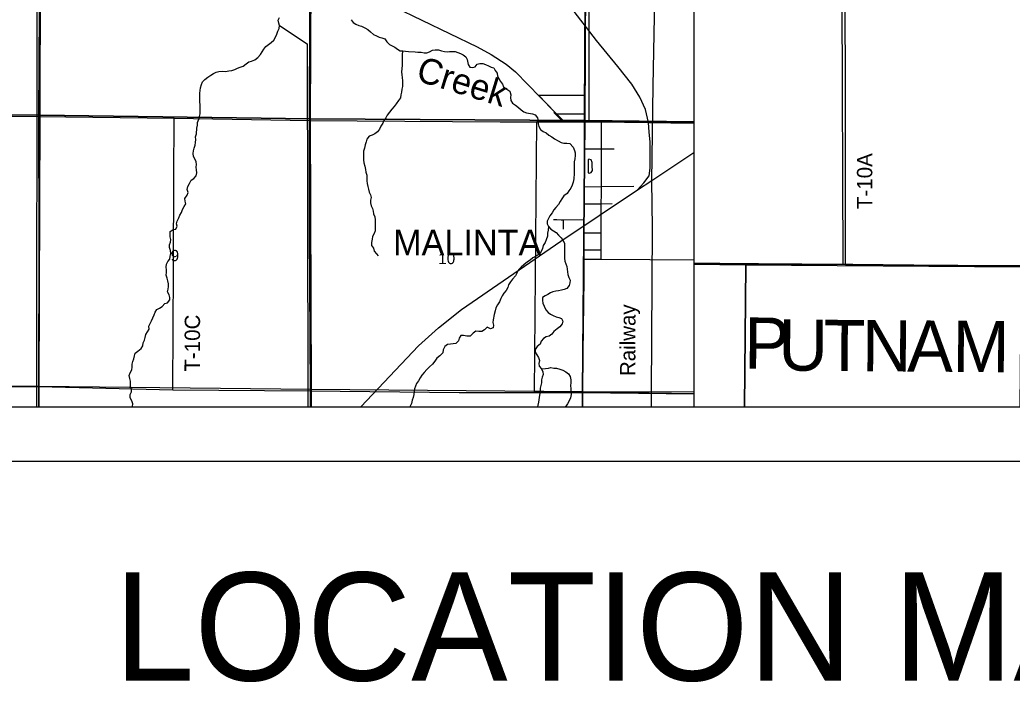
# Model space of a CAD drawing. Extents: x -6.2 to 37.4, y 0.2 to 22.2.
# Drawn here: x 3.834 to 5.67, y 13.798 to 15.024 of the extents above; entities that cross this region are included whole.
import ezdxf

# ---------------------------------------------------------------- set-up
doc = ezdxf.new("R2010")
doc.units = 0
for name, color, linetype in [('GM_X_City_Street', 7, 'Continuous'), ('GM_X_Corporation', 7, 'Continuous'), ('GM_X_Corporation_Text', 7, 'Continuous'), ('GM_X_County_Road', 7, 'Continuous'), ('GM_X_County_Text', 7, 'Continuous'), ('GM_X_Minor_Lake', 7, 'Continuous'), ('GM_X_Minor_River', 7, 'Continuous'), ('GM_X_Minor_River_Text', 7, 'Continuous'), ('GM_X_Rail_Line', 7, 'Continuous'), ('GM_X_Rail_Line_Text', 7, 'Continuous'), ('GM_X_Section', 7, 'Continuous'), ('GM_X_Section_Text', 7, 'Continuous'), ('GM_X_State_Route', 7, 'Continuous'), ('GM_X_Township_Road', 7, 'Continuous'), ('GM_X_Township_Road_Text', 7, 'Continuous'), ('GM_X_US_Shield', 7, 'Continuous'), ('SH_Border', 7, 'Continuous'), ('SH_Cut_Line', 7, 'Continuous'), ('SH_Data', 7, 'Continuous'), ('SH_Text', 7, 'Continuous')]:
    doc.layers.add(name, color=color, linetype=linetype)

msp = doc.modelspace()

# ---------------------------------------------------------------- linework, layer by layer
at = {"layer": 'GM_X_City_Street'}
for p, q in [((4.8397, 14.6538), (4.8779, 14.6545)), ((4.8397, 14.6365), (4.8397, 14.6538)), ((4.8779, 14.6294), (4.9092, 14.6294)), ((4.8777, 14.5983), (4.909, 14.5983))]:
    msp.add_line(p, q, dxfattribs=at)
for points in [[(4.909, 14.5807), (4.909, 14.5983), (4.9092, 14.6294), (4.9094, 14.6833), (4.9095, 14.7017), (4.9095, 14.7152), (4.9095, 14.785), (4.9096, 14.8348)], [(4.8784, 14.7848), (4.9095, 14.785), (4.933, 14.7851)], [(4.8782, 14.7148), (4.9095, 14.7152), (4.9695, 14.7159)], [(4.8781, 14.6829), (4.9094, 14.6833), (4.9292, 14.6836)], [(4.8207, 14.6542), (4.8272, 14.654), (4.835, 14.6537), (4.8397, 14.6538)], [(4.8777, 14.5808), (4.909, 14.5807), (4.9991, 14.5804), (5.0809, 14.5799)]]:
    msp.add_lwpolyline(points, dxfattribs=at)
at = {"layer": 'GM_X_Corporation'}
msp.add_lwpolyline([(5.0809, 14.3317), (4.8749, 14.3347), (4.7857, 14.3347), (4.7899, 14.8354), (4.8382, 14.8354), (4.8216, 14.8523), (4.8242, 14.8523), (4.793, 14.8843), (4.8787, 14.8843), (4.8785, 14.8493), (4.8271, 14.8493), (4.8407, 14.8354), (4.8785, 14.8354), (5.0809, 14.8328)], dxfattribs=at)
at = {"layer": 'GM_X_County_Road'}
for p, q in [((4.7964, 14.8806), (4.8237, 14.8526)), ((4.8237, 14.8526), (4.8271, 14.8491)), ((4.8271, 14.8491), (4.8407, 14.8351)), ((4.836, 14.8351), (4.8407, 14.8351)), ((4.8407, 14.8351), (4.8786, 14.8352))]:
    msp.add_line(p, q, dxfattribs=at)
for points in [[(4.3712, 15.2058), (4.4704, 15.1311), (4.475, 15.1261), (4.4823, 15.114), (4.5079, 15.0602), (4.5117, 15.0558), (4.5262, 15.0474), (4.6796, 14.9736), (4.7056, 14.9596), (4.7333, 14.9416), (4.7507, 14.9275), (4.7964, 14.8806)], [(3.3737, 14.8502), (3.5993, 14.8481), (3.6217, 14.8478), (3.869, 14.8445), (4.1193, 14.8414), (4.3697, 14.8376), (4.7222, 14.8351), (4.7789, 14.8351)], [(4.7789, 14.8351), (4.7975, 14.8351), (4.8265, 14.8351)], [(4.8265, 14.8351), (4.8312, 14.8351), (4.836, 14.8351)], [(4.8786, 14.8352), (4.9096, 14.8348), (5.0809, 14.8325)], [(5.0809, 14.5729), (5.129, 14.5725), (5.2005, 14.5717), (5.3613, 14.5708)], [(5.3613, 14.5708), (5.3746, 14.5707), (5.488, 14.5696), (5.5689, 14.569), (5.6863, 14.5681)]]:
    msp.add_lwpolyline(points, dxfattribs=at)
at = {"layer": 'GM_X_Minor_Lake'}
msp.add_line((4.885, 14.7624), (4.8854, 14.7408), dxfattribs=at)
msp.add_lwpolyline([(4.8854, 14.7408), (4.8867, 14.7402), (4.8906, 14.7412), (4.893, 14.7449), (4.8928, 14.7527), (4.8927, 14.7599), (4.8907, 14.7645), (4.8866, 14.7656), (4.885, 14.7649), (4.885, 14.7624)], dxfattribs=at)
at = {"layer": 'GM_X_Minor_River'}
msp.add_line((3.8653, 15.2244), (3.8642, 14.3074), dxfattribs=at)
for points in [[(4.8897, 16.0915), (4.8869, 16.0485), (4.8784, 15.3818), (4.886, 15.3582), (4.8861, 14.8386)], [(5.4281, 15.4944), (5.3538, 15.4752), (5.3544, 15.0595), (5.3561, 14.5724)], [(4.1816, 14.9173), (4.187, 14.9211), (4.1919, 14.9244), (4.1967, 14.9269), (4.202, 14.9279), (4.2077, 14.9287), (4.2142, 14.9283), (4.2201, 14.9291), (4.226, 14.9296), (4.2313, 14.932), (4.2365, 14.9339), (4.2415, 14.936), (4.2467, 14.9381), (4.2521, 14.942), (4.257, 14.9456), (4.2625, 14.947), (4.2683, 14.9497), (4.2739, 14.9542), (4.2788, 14.9592), (4.2818, 14.9641), (4.2852, 14.9695), (4.2886, 14.9745), (4.2986, 14.9818), (4.3035, 14.9862), (4.3067, 14.9914), (4.3088, 14.9972), (4.3112, 15.0027), (4.3135, 15.0075), (4.3142, 15.0128), (4.3126, 15.0176), (4.3114, 15.0228), (4.3139, 15.0276)], [(4.4463, 15.0237), (4.4503, 15.0187), (4.4553, 15.0153), (4.4606, 15.0131), (4.466, 15.0118), (4.4722, 15.0088), (4.4774, 15.0054), (4.4822, 15.0014), (4.4881, 14.9967), (4.4932, 14.9939), (4.4984, 14.9917), (4.5033, 14.9902), (4.5086, 14.9883), (4.5127, 14.9827), (4.5173, 14.9778), (4.5222, 14.9756), (4.5271, 14.9732), (4.5322, 14.9691), (4.5375, 14.9661), (4.5422, 14.9661), (4.5473, 14.9658), (4.5528, 14.965)], [(4.3142, 15.0128), (4.3655, 14.9791), (4.3665, 14.3408), (4.3664, 14.3074)], [(4.5422, 14.9661), (4.5411, 14.9608), (4.5409, 14.9559), (4.541, 14.9498), (4.5408, 14.9445), (4.541, 14.9394), (4.5405, 14.9333), (4.5397, 14.9269), (4.5401, 14.9222), (4.5409, 14.9166), (4.5415, 14.9111), (4.5413, 14.9054), (4.5414, 14.9001), (4.5406, 14.8952), (4.5397, 14.8899), (4.5388, 14.885), (4.5377, 14.8794), (4.5339, 14.8742), (4.5296, 14.8684), (4.5264, 14.8634), (4.5221, 14.8584), (4.5176, 14.853), (4.5132, 14.8475), (4.511, 14.8426), (4.5068, 14.8374), (4.5054, 14.8325), (4.5018, 14.8267), (4.4993, 14.8211), (4.4954, 14.8161), (4.4905, 14.8125), (4.4852, 14.8105), (4.4798, 14.8082), (4.4757, 14.8028), (4.4742, 14.7976), (4.4725, 14.7923), (4.471, 14.7863), (4.4695, 14.7804), (4.4692, 14.7704), (4.4692, 14.7645), (4.4703, 14.7588), (4.4717, 14.7529), (4.4734, 14.7468), (4.4738, 14.7418), (4.4757, 14.7361), (4.4758, 14.7313), (4.4756, 14.726), (4.476, 14.7209), (4.4772, 14.7153), (4.4784, 14.7106), (4.4801, 14.7048), (4.4826, 14.6998), (4.4838, 14.6949), (4.4825, 14.69), (4.4825, 14.6848), (4.4839, 14.6797), (4.4862, 14.6745), (4.4876, 14.6697), (4.4882, 14.6649), (4.4901, 14.6592), (4.4909, 14.6537), (4.4913, 14.6485), (4.4913, 14.6434), (4.491, 14.6381), (4.4912, 14.6334), (4.489, 14.6285), (4.4863, 14.6229), (4.4854, 14.6176), (4.4841, 14.6118), (4.4843, 14.6063), (4.4881, 14.601), (4.4891, 14.5957), (4.4933, 14.5908), (4.4968, 14.5871)], [(4.5528, 14.965), (4.5649, 14.9647), (4.5702, 14.9638), (4.5763, 14.9636), (4.5815, 14.9623), (4.5865, 14.9627), (4.5914, 14.9641), (4.5968, 14.9672), (4.6022, 14.9683), (4.6082, 14.9678), (4.6135, 14.9661), (4.6192, 14.965), (4.6241, 14.9647), (4.6288, 14.9653), (4.634, 14.9653), (4.6389, 14.965), (4.6438, 14.9631), (4.6488, 14.9613), (4.6537, 14.9591), (4.6585, 14.9553), (4.6614, 14.9505), (4.663, 14.941), (4.6659, 14.9359), (4.6708, 14.9354), (4.6759, 14.9364), (4.6799, 14.9414), (4.6847, 14.9428), (4.6902, 14.9426), (4.6954, 14.941), (4.7005, 14.9385), (4.7055, 14.9363), (4.7104, 14.9346), (4.7133, 14.9298), (4.7167, 14.925), (4.7175, 14.9196), (4.72, 14.9148), (4.7231, 14.9098), (4.7267, 14.9048), (4.7287, 14.8996), (4.7344, 14.8954), (4.7402, 14.8918), (4.7421, 14.8851), (4.7417, 14.8802), (4.7418, 14.8745), (4.7452, 14.8695), (4.7504, 14.8657), (4.7562, 14.8612), (4.7611, 14.8571), (4.766, 14.8535), (4.771, 14.8513), (4.782, 14.8498), (4.7869, 14.848), (4.7914, 14.8422), (4.7924, 14.8368), (4.7924, 14.8313), (4.7938, 14.8262), (4.797, 14.8206), (4.8018, 14.817), (4.8075, 14.8144), (4.8126, 14.8102), (4.818, 14.8071), (4.8231, 14.8035), (4.8294, 14.7999), (4.835, 14.7967), (4.8403, 14.7956), (4.8457, 14.7952), (4.8509, 14.7951), (4.8571, 14.7879), (4.8601, 14.7821), (4.8611, 14.7773), (4.8612, 14.7724), (4.8602, 14.7664), (4.8595, 14.7609), (4.859, 14.7558), (4.859, 14.7448), (4.859, 14.7395), (4.8587, 14.7294), (4.8572, 14.7232), (4.8554, 14.7178), (4.8529, 14.7123), (4.8495, 14.7073), (4.846, 14.7025), (4.8403, 14.6977), (4.8364, 14.6925), (4.8334, 14.6875), (4.8304, 14.6817), (4.8255, 14.6767), (4.8217, 14.6719), (4.8185, 14.6665), (4.8142, 14.6611), (4.809, 14.651), (4.8092, 14.6463), (4.8117, 14.6415), (4.8161, 14.6364), (4.8211, 14.633), (4.826, 14.6304), (4.8304, 14.6252), (4.835, 14.6203), (4.8388, 14.6151), (4.8411, 14.6097), (4.8413, 14.6042)], [(4.052, 14.4108), (4.0578, 14.4154), (4.0614, 14.4206), (4.0619, 14.4259), (4.0643, 14.4309), (4.0652, 14.4362), (4.0665, 14.4415), (4.0697, 14.4463), (4.0729, 14.4516), (4.0721, 14.4567), (4.0747, 14.4619), (4.0772, 14.467), (4.0796, 14.4726), (4.0822, 14.4776), (4.0841, 14.4827), (4.0871, 14.4879), (4.0919, 14.4903), (4.0967, 14.4935), (4.1016, 14.4987), (4.1068, 14.5001), (4.1109, 14.5053), (4.1111, 14.51), (4.1101, 14.5151), (4.1065, 14.5204), (4.1078, 14.5253), (4.1085, 14.5302), (4.1086, 14.5349), (4.1075, 14.5405), (4.1061, 14.5454), (4.1046, 14.5513), (4.1047, 14.5563), (4.1047, 14.5612), (4.1043, 14.5662), (4.105, 14.5714), (4.1076, 14.5763), (4.1111, 14.5811), (4.1119, 14.5862), (4.1128, 14.5913), (4.1124, 14.5966), (4.1103, 14.6022), (4.1108, 14.6073), (4.1121, 14.6122), (4.1128, 14.6173), (4.1118, 14.6221), (4.1118, 14.6274), (4.1116, 14.6323), (4.1173, 14.6356), (4.1223, 14.6364), (4.1245, 14.6416), (4.1234, 14.6464), (4.1246, 14.6513), (4.128, 14.6571), (4.1299, 14.662), (4.1325, 14.6674), (4.1348, 14.673), (4.1376, 14.6782), (4.1406, 14.6831), (4.1392, 14.6882), (4.139, 14.693), (4.1432, 14.6991), (4.1448, 14.7042), (4.1431, 14.7097), (4.1444, 14.7154), (4.1478, 14.7208), (4.1504, 14.7268), (4.1555, 14.7303), (4.16, 14.7352), (4.1613, 14.7407), (4.1605, 14.746), (4.1601, 14.7508), (4.1604, 14.7559), (4.1596, 14.7607), (4.1577, 14.7655), (4.1548, 14.7709), (4.1542, 14.7762), (4.1551, 14.7811), (4.1562, 14.7862), (4.1577, 14.7918), (4.1583, 14.7969), (4.159, 14.8022), (4.1584, 14.8072), (4.1604, 14.8126), (4.1608, 14.8234), (4.1621, 14.8289), (4.1626, 14.8338), (4.1648, 14.8396), (4.1663, 14.8447), (4.1674, 14.8496), (4.167, 14.8547), (4.167, 14.8597), (4.167, 14.8661), (4.1668, 14.8716), (4.1666, 14.8771), (4.1665, 14.8821), (4.1669, 14.8877), (4.1672, 14.8927), (4.1681, 14.8981), (4.1694, 14.9038), (4.1717, 14.9087), (4.176, 14.9135), (4.1816, 14.9173)], [(4.8117, 14.6415), (4.8113, 14.6345), (4.81, 14.629), (4.8098, 14.6233), (4.8074, 14.6169), (4.8057, 14.6117), (4.8021, 14.6059), (4.8004, 14.6004), (4.798, 14.5952), (4.7942, 14.5902), (4.7888, 14.5864), (4.7828, 14.5831), (4.7778, 14.5791), (4.7728, 14.576), (4.7663, 14.5705), (4.7614, 14.5659), (4.7564, 14.5611), (4.7538, 14.5561), (4.7505, 14.5501), (4.7449, 14.544), (4.7415, 14.539), (4.7377, 14.5332), (4.7362, 14.5283), (4.7336, 14.5231), (4.7289, 14.5179), (4.7259, 14.5127), (4.7237, 14.5079), (4.7212, 14.502), (4.7174, 14.4963), (4.7144, 14.4911), (4.7133, 14.485), (4.7114, 14.4782), (4.7092, 14.4684), (4.709, 14.4635), (4.7102, 14.4586), (4.7093, 14.4536), (4.7041, 14.4517), (4.6984, 14.4551), (4.6935, 14.4503), (4.6881, 14.4471), (4.6826, 14.447), (4.6775, 14.4476), (4.6722, 14.4441), (4.667, 14.4386), (4.6605, 14.4386), (4.6547, 14.4397), (4.6497, 14.4396), (4.6465, 14.4346), (4.6449, 14.4295), (4.64, 14.4248), (4.6352, 14.4239), (4.6301, 14.4233), (4.6248, 14.4229), (4.6199, 14.4191), (4.6169, 14.4133), (4.616, 14.4076), (4.6109, 14.4023), (4.6052, 14.3975), (4.6016, 14.3919), (4.5969, 14.3868), (4.5913, 14.3814), (4.5868, 14.3766), (4.5819, 14.3711), (4.5773, 14.3661), (4.5745, 14.3612), (4.571, 14.356), (4.5676, 14.3508), (4.5654, 14.3459), (4.5637, 14.3409), (4.5633, 14.3358), (4.5624, 14.3303), (4.5611, 14.3248), (4.5596, 14.3199), (4.5581, 14.3139), (4.5555, 14.3087), (4.5552, 14.3074)], [(4.8413, 14.6042), (4.8415, 14.5979), (4.8415, 14.593), (4.8414, 14.5877), (4.8414, 14.5827), (4.842, 14.5774), (4.8438, 14.5724), (4.8455, 14.5673), (4.8463, 14.5625), (4.8471, 14.5574), (4.8477, 14.5524), (4.8494, 14.5472), (4.8517, 14.542), (4.8514, 14.5369), (4.8499, 14.5319), (4.8454, 14.5267), (4.8406, 14.5247), (4.8356, 14.5234), (4.8301, 14.5224), (4.8251, 14.5214), (4.82, 14.5204), (4.8152, 14.5183), (4.8104, 14.5152), (4.8056, 14.5132), (4.8005, 14.5102), (4.8005, 14.5043), (4.8015, 14.4995), (4.8038, 14.4936), (4.8068, 14.4872), (4.8109, 14.4822), (4.8157, 14.4788), (4.8206, 14.4768), (4.8258, 14.4743), (4.8307, 14.4729), (4.8359, 14.4712), (4.8383, 14.466), (4.8368, 14.4609), (4.8328, 14.4559), (4.8276, 14.4521), (4.8217, 14.4468), (4.8176, 14.4418), (4.8128, 14.4385), (4.8074, 14.4371), (4.8022, 14.4341), (4.7984, 14.4289), (4.796, 14.4238), (4.7908, 14.4192), (4.787, 14.4136), (4.787, 14.4089), (4.7903, 14.4041), (4.7932, 14.3987), (4.7953, 14.3931), (4.7936, 14.388), (4.7942, 14.3829), (4.7986, 14.3778), (4.8015, 14.3726), (4.8019, 14.3677), (4.7997, 14.3628), (4.7987, 14.3575), (4.799, 14.3522), (4.7975, 14.3473), (4.7964, 14.3424), (4.7961, 14.3375), (4.7938, 14.3209)], [(4.0421, 14.3074), (4.0422, 14.3081), (4.0429, 14.3134), (4.0408, 14.319), (4.0378, 14.3244), (4.0378, 14.3302), (4.04, 14.3353), (4.0403, 14.3404), (4.0386, 14.3452), (4.0382, 14.35), (4.0381, 14.3549), (4.0373, 14.3602), (4.036, 14.3658), (4.0379, 14.3708), (4.0407, 14.3764), (4.0414, 14.3813), (4.0414, 14.3868), (4.0425, 14.3917), (4.0447, 14.3966), (4.046, 14.4019), (4.0467, 14.407), (4.052, 14.4108)], [(4.7986, 14.3778), (4.8064, 14.3784), (4.8115, 14.3794), (4.8163, 14.3804), (4.8214, 14.3794), (4.8267, 14.3791), (4.8327, 14.3776), (4.8384, 14.3755), (4.8436, 14.3727), (4.8488, 14.3688), (4.8515, 14.3638), (4.8532, 14.3578), (4.853, 14.3525), (4.8526, 14.3463), (4.8529, 14.3414), (4.8529, 14.3359), (4.8537, 14.3303), (4.8524, 14.3243), (4.8499, 14.3187), (4.8469, 14.3129), (4.8429, 14.3077), (4.8428, 14.3074)], [(4.7938, 14.3209), (4.7931, 14.316), (4.7922, 14.3107), (4.7915, 14.3074)]]:
    msp.add_lwpolyline(points, dxfattribs=at)
at = {"layer": 'GM_X_Rail_Line'}
for p, q in [((5.0027, 14.7261), (5.0809, 14.7782)), ((4.9765, 14.7094), (5.0027, 14.7261))]:
    msp.add_line(p, q, dxfattribs=at)
for points in [[(5.0025, 14.3074), (5.0025, 14.3335), (5.0039, 14.639), (5.0028, 14.7258), (5.0054, 14.9018), (5.0142, 15.3507), (5.0314, 16.3553), (5.0343, 16.5004), (5.0358, 16.5978), (5.0401, 16.8553), (5.0435, 17.1071), (5.0536, 17.6004), (5.0579, 17.8816), (5.0677, 18.5001), (5.0692, 18.5857), (5.0746, 18.8476), (5.0809, 19.3027)], [(5.0809, 17.5845), (5.0809, 14.5732), (5.1289, 14.5727), (5.2004, 14.572), (5.3612, 14.571), (5.3745, 14.5709), (5.4879, 14.5699), (5.5688, 14.5693), (5.6862, 14.5684)], [(4.9765, 14.7094), (4.9883, 14.7219), (4.9981, 14.7352), (5, 14.7492), (5, 14.7982), (4.9981, 14.816), (4.9968, 14.8334), (4.9909, 14.858), (4.9808, 14.8805), (4.9659, 14.9044), (4.94, 14.9373), (4.9005, 14.9855), (4.7108, 15.2324), (4.5158, 15.4915), (4.3437, 15.7115)], [(5.0809, 15.3507), (4.8814, 15.3529), (4.368, 15.3592), (3.8713, 15.3657), (3.3654, 15.3683), (2.872, 15.3742), (2.8725, 14.8583), (2.8721, 14.3543), (2.8719, 14.3074), (5.0809, 14.3074)], [(4.4646, 14.3074), (4.5712, 14.4208), (4.6083, 14.4538), (4.6508, 14.4875), (4.8347, 14.6142), (4.9765, 14.7094)], [(5.6862, 14.5684), (5.5688, 14.5693), (5.4879, 14.5699), (5.3745, 14.5709), (5.3612, 14.571), (5.2004, 14.572), (5.1289, 14.5727), (5.0809, 14.5732), (5.0809, 14.3074), (7.1878, 14.3074)]]:
    msp.add_lwpolyline(points, dxfattribs=at)
at = {"layer": 'GM_X_Section'}
for points in [[(3.8652, 15.3662), (3.8718, 15.3661), (3.8704, 14.8473), (3.3743, 14.8525), (3.3746, 15.3703)], [(3.8718, 15.3661), (4.3675, 15.3588), (4.373, 15.3585), (4.3708, 14.8405), (3.8704, 14.8473)], [(4.373, 15.3585), (4.8727, 15.3534), (4.8812, 15.3533), (4.8791, 14.8372), (4.3708, 14.8405)], [(3.3743, 14.8525), (3.8704, 14.8473), (3.8689, 14.3453), (3.3709, 14.3507)], [(4.3708, 14.8405), (4.3725, 14.3396), (3.8689, 14.3453), (3.8704, 14.8473)], [(4.8791, 14.8372), (4.8749, 14.3354), (4.3725, 14.3396), (4.3708, 14.8405)]]:
    msp.add_lwpolyline(points, close=True, dxfattribs=at)
for points in [[(5.0809, 14.8352), (4.8791, 14.8372), (4.8812, 15.3533), (5.0809, 15.3506)], [(5.0809, 14.3345), (4.8749, 14.3354), (4.8791, 14.8372), (5.0809, 14.8352)]]:
    msp.add_lwpolyline(points, dxfattribs=at)
at = {"layer": 'GM_X_State_Route'}
msp.add_line((4.875, 14.3074), (4.875, 14.3344), dxfattribs=at)
for points in [[(4.8791, 14.9557), (4.8801, 15.1803), (4.8816, 15.3526)], [(4.8786, 14.8352), (4.8786, 14.8552), (4.8791, 14.9557)], [(4.8782, 14.721), (4.8782, 14.7234), (4.8784, 14.7848), (4.8786, 14.8352)], [(4.8781, 14.6814), (4.8781, 14.6829), (4.8781, 14.6835), (4.8781, 14.684), (4.8782, 14.7148), (4.8782, 14.721)], [(4.8779, 14.6417), (4.8779, 14.6436), (4.8779, 14.6545), (4.8781, 14.6814)], [(4.8778, 14.6171), (4.8779, 14.6294), (4.8779, 14.6417)], [(4.8777, 14.5823), (4.8777, 14.5839), (4.8777, 14.5983), (4.8778, 14.6171)], [(4.875, 14.3344), (4.8756, 14.4071), (4.8775, 14.5445), (4.8777, 14.5808), (4.8777, 14.5823)]]:
    msp.add_lwpolyline(points, dxfattribs=at)
at = {"layer": 'GM_X_Township_Road'}
for p, q in [((5.3613, 14.5708), (5.3613, 14.7616)), ((3.8686, 14.3074), (3.8685, 14.3451)), ((4.3714, 14.3074), (4.3714, 14.3371)), ((4.875, 14.3344), (5.0809, 14.3314))]:
    msp.add_line(p, q, dxfattribs=at)
for points in [[(3.869, 14.8445), (3.8703, 15.1395), (3.8714, 15.3654)], [(4.3697, 14.8376), (4.3704, 15.0375), (4.3712, 15.2058)], [(5.3613, 14.7616), (5.3613, 14.7636), (5.3611, 14.8884), (5.3607, 15.0673)], [(3.8685, 14.3451), (3.8692, 14.6151), (3.869, 14.8445)], [(4.1169, 14.3393), (4.118, 14.5634), (4.1186, 14.7332), (4.1193, 14.8414)], [(4.3714, 14.3371), (4.3695, 14.6293), (4.3697, 14.8376)], [(5.0809, 14.5729), (5.129, 14.5725), (5.2005, 14.5717), (5.3613, 14.5708)], [(5.3613, 14.5708), (5.3746, 14.5707), (5.488, 14.5696), (5.5689, 14.569), (5.6863, 14.5681)], [(2.8688, 14.3541), (2.8723, 14.354), (3.0841, 14.351), (3.3711, 14.3493), (3.6211, 14.3439), (3.8685, 14.3451), (4.1169, 14.3393), (4.3714, 14.3371), (4.6467, 14.3343), (4.7944, 14.3344)], [(4.7944, 14.3344), (4.7949, 14.3344), (4.875, 14.3344)]]:
    msp.add_lwpolyline(points, dxfattribs=at)
at = {"layer": 'GM_X_US_Shield'}
for points in [[(5.0809, 14.5711), (5.0809, 14.3074), (5.1745, 14.3074), (5.1769, 14.57)], [(5.1745, 14.3074), (5.6844, 14.3074), (5.6866, 14.5661), (5.6845, 14.5662), (5.1769, 14.57)], [(3.3708, 14.3074), (3.8688, 14.3074), (3.8689, 14.3453), (3.3709, 14.3507)], [(3.8688, 14.3074), (4.3725, 14.3074), (4.3725, 14.3396), (3.8689, 14.3453)], [(4.3725, 14.3074), (4.8749, 14.3074), (4.8749, 14.3354), (4.3725, 14.3396)]]:
    msp.add_lwpolyline(points, close=True, dxfattribs=at)
msp.add_lwpolyline([(5.0809, 14.3345), (4.8749, 14.3354), (4.8749, 14.3074), (5.0809, 14.3074)], dxfattribs=at)
at = {"layer": 'SH_Border'}
msp.add_line((5.0809, 21.1074), (5.0809, 14.3074), dxfattribs=at)
at = {"layer": 'SH_Cut_Line'}
for points in [[(1.6809, 20.3973), (1.6809, 14.3074), (5.0809, 14.3074)], [(5.0809, 17.7074), (5.0809, 14.5732), (5.1289, 14.5727), (5.2004, 14.572), (5.3612, 14.571), (5.3745, 14.5709), (5.4879, 14.5699), (5.5688, 14.5693), (5.6862, 14.5684)], [(5.6862, 14.5684), (5.5688, 14.5693), (5.4879, 14.5699), (5.3745, 14.5709), (5.3612, 14.571), (5.2004, 14.572), (5.1289, 14.5727), (5.0809, 14.5732), (5.0809, 14.3074), (8.4809, 14.3074)]]:
    msp.add_lwpolyline(points, dxfattribs=at)
at = {"layer": 'SH_Data'}
for p, q in [((1.6809, 14.3074), (8.4809, 14.3074)), ((1.5809, 14.2074), (8.5809, 14.2074))]:
    msp.add_line(p, q, dxfattribs=at)

# ---------------------------------------------------------------- texts
at = {"layer": 'GM_X_Corporation_Text'}
msp.add_text('MALINTA', height=0.04735, rotation=0, dxfattribs=at).set_placement((4.5241, 14.5879))
at = {"layer": 'GM_X_County_Text'}
for s, rotation, p in [('P', 359.6042, (5.1736, 14.3784)), ('U', 359.5629, (5.2368, 14.3748)), ('T', 359.568, (5.3205, 14.3741)), ('N', 359.565, (5.3914, 14.3736)), ('A', 359.565, (5.4751, 14.373)), ('M', 359.5753, (5.5589, 14.3723))]:
    msp.add_text(s, height=0.0947, rotation=rotation, dxfattribs=at).set_placement(p)
at = {"layer": 'GM_X_Minor_River_Text'}
msp.add_text('Creek', height=0.04737, rotation=342.9218, dxfattribs=at).set_placement((4.5645, 14.9118))
at = {"layer": 'GM_X_Rail_Line_Text'}
msp.add_text('Railway', height=0.02831, rotation=89.8452, dxfattribs=at).set_placement((4.9724, 14.3646))
at = {"layer": 'GM_X_Section_Text'}
for s, height, p in [('9', 0.0209, (4.1127, 14.5771)), ('10', 0.02093, (4.6079, 14.5717))]:
    msp.add_text(s, height=height, rotation=0, dxfattribs=at).set_placement(p)
at = {"layer": 'GM_X_Township_Road_Text'}
for s, rotation, p in [('T-10A', 90, (5.4108, 14.6734)), ('T-10C', 89.7373, (4.1666, 14.3727))]:
    msp.add_text(s, height=0.02841, rotation=rotation, dxfattribs=at).set_placement(p)
at = {"layer": 'SH_Text'}
msp.add_text('LOCATION MAP', height=0.2, dxfattribs=at).set_placement((4.0078, 13.8012))

doc.saveas('drawing.dxf')
